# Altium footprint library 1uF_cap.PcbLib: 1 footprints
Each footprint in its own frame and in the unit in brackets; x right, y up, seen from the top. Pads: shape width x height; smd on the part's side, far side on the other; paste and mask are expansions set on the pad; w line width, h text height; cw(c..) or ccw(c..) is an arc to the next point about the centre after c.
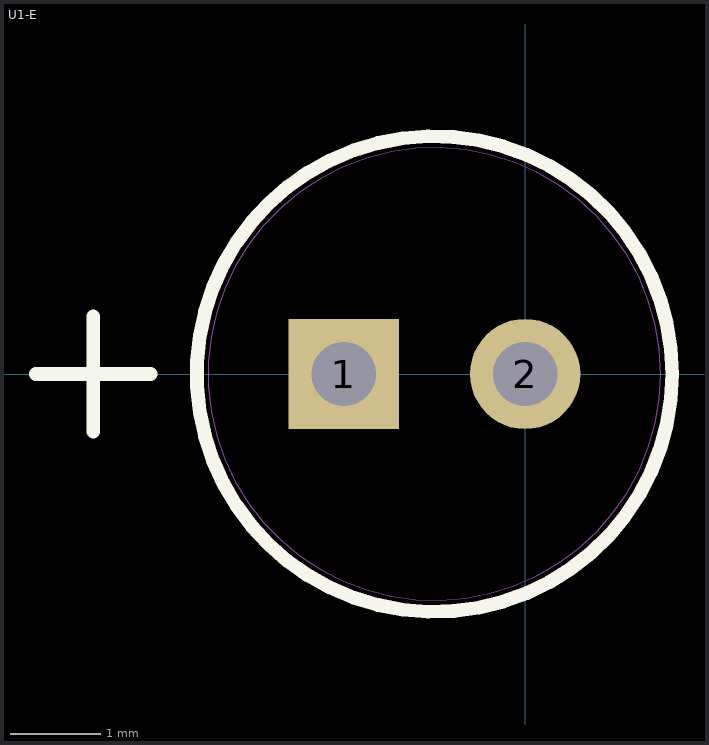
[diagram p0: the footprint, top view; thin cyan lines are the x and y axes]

## U1-E [mil]
pads (2):
  rect 48x48 / inner round 60 / far side rect 48x48 hole 28 paste+0: 1(-79,0)
  round 48 / inner round 60 / far side round 48 hole 28 paste+0: 2(0,0)
Top Overlay:
  circle w6: c-39.5,0 r103.5
  lines w6: -213,0 -163,0 ; -188,-25 -188,25
Mechanical 13:
  circle w0: c-39.5,0 r98.5
3D body "U1-E.step": height 427.99, standoff -149.02, extent -137.99,-98.37 59.01,98.38
3D body: height 10, standoff 0, extent 0,0 10,10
